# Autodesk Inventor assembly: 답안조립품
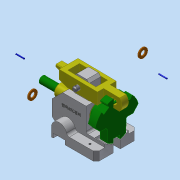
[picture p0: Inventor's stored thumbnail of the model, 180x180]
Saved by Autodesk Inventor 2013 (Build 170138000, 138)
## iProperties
Created: 2016-11
Part Number: 답안조립품
Document SubType Name: Assembly
Designer: Administrator
Author: Administrator
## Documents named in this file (8)
- C:\Users\Administrator\Desktop\461108V1020\답안조립품.iam
- C:\Users\Administrator\Desktop\461108V1020\본체.ipt
- C:\Users\Administrator\Desktop\461108V1020 (2)\분할축.ipt
- C:\Users\Administrator\Desktop\461108V1020 (2)\부시.ipt
- C:\Users\Administrator\Desktop\461108V1020 (2)\분할대.ipt
- C:\Users\Administrator\Desktop\461108V1020 (2)\클레비스핀.ipt
- C:\Users\Administrator\Desktop\461108V1020 (2)\와셔.ipt
- C:\Users\Administrator\Desktop\461108V1020 (2)\원통형핀.ipt
